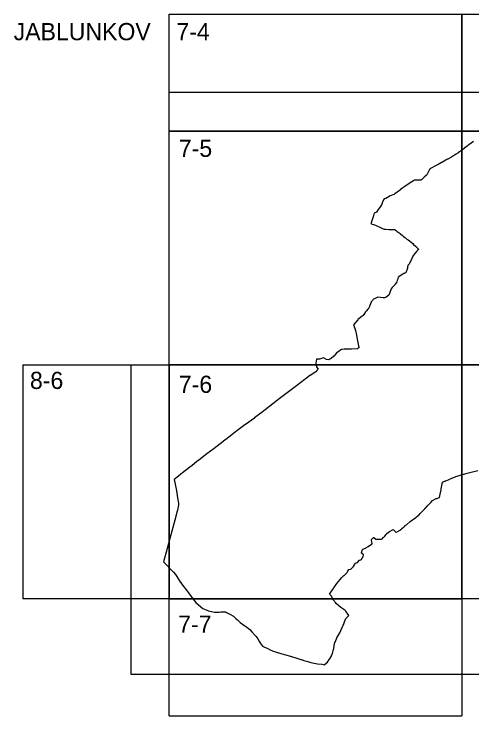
# Model space of a CAD drawing. Extents: x -449577 to -436680, y -1132317 to -1125726.
# Drawn here: x -444031.6 to -443787.2, y -1131943.6 to -1131568.6 of the extents above; entities that cross this region are included whole.
import ezdxf

# ---------------------------------------------------------------- set-up
doc = ezdxf.new("R2010")
doc.units = 0
for name, color, linetype in [('Vrstva 1', 7, 'Continuous'), ('Vrstva 10', 7, 'Continuous'), ('Vrstva 4', 7, 'Continuous')]:
    doc.layers.add(name, color=color, linetype=linetype)

msp = doc.modelspace()

# ---------------------------------------------------------------- linework, layer by layer
at = {"layer": 'Vrstva 1'}
for points in [[(-443786.38, -1131636.64), (-443787.59, -1131637.6), (-443787.59, -1131637.6), (-443788.74, -1131638.47), (-443789.31, -1131638.9), (-443789.89, -1131639.34), (-443790.05, -1131639.46), (-443792.18, -1131641.1), (-443793.25, -1131641.92), (-443793.72, -1131642.26), (-443794.48, -1131642.77), (-443794.73, -1131642.93), (-443795.32, -1131643.32), (-443795.36, -1131643.35), (-443795.57, -1131643.49), (-443796.48, -1131644.09), (-443796.49, -1131644.09), (-443796.96, -1131644.35), (-443797.11, -1131644.43), (-443797.29, -1131644.53), (-443797.75, -1131644.78), (-443797.93, -1131644.89), (-443798.09, -1131644.98), (-443798.19, -1131645.04), (-443798.43, -1131645.18), (-443800.09, -1131646.12), (-443800.26, -1131646.21), (-443800.49, -1131646.34), (-443802.96, -1131647.74), (-443803.08, -1131647.81), (-443805.19, -1131648.94), (-443806.21, -1131649.49), (-443809.55, -1131651.3), (-443809.72, -1131651.6), (-443809.78, -1131651.71), (-443810.56, -1131653.17), (-443811.24, -1131654.49), (-443811.38, -1131654.62), (-443811.47, -1131654.7), (-443812.61, -1131655.74), (-443814.12, -1131657.12), (-443814.29, -1131657.27), (-443814.29, -1131657.28), (-443814.76, -1131657.29), (-443817.95, -1131657.38), (-443817.96, -1131657.38), (-443818.39, -1131657.67), (-443819.22, -1131658.24), (-443821.69, -1131659.9), (-443821.73, -1131659.92), (-443821.97, -1131660.1), (-443822.24, -1131660.3), (-443825.22, -1131662.43), (-443825.29, -1131662.48), (-443828.29, -1131664.66), (-443828.76, -1131665), (-443828.92, -1131665.06), (-443830.86, -1131665.78), (-443830.87, -1131665.78), (-443831.26, -1131666.02), (-443833.14, -1131667.18), (-443834.06, -1131667.39), (-443834.31, -1131667.9), (-443835.07, -1131669.41), (-443835.08, -1131669.42), (-443835.15, -1131669.68), (-443835.35, -1131670.52), (-443836.18, -1131671.63), (-443837.55, -1131673.58), (-443838.11, -1131674.39), (-443838.14, -1131674.41), (-443839.3, -1131675.05), (-443839.4, -1131675.11), (-443839.47, -1131675.5), (-443839.62, -1131676.31), (-443839.67, -1131676.5), (-443840.96, -1131680.08), (-443841.13, -1131680.56), (-443841.1, -1131680.55), (-443841.08, -1131680.54), (-443840.4, -1131680.8), (-443838.59, -1131681.46), (-443837.97, -1131681.75), (-443835.68, -1131682.83), (-443835.66, -1131682.83), (-443834.5, -1131683.3), (-443834.03, -1131683.48), (-443834, -1131683.49), (-443833.57, -1131683.52), (-443833.43, -1131683.53), (-443833.21, -1131683.55), (-443831.61, -1131683.65), (-443830.57, -1131683.72), (-443829.52, -1131683.69), (-443828.68, -1131683.66), (-443828.67, -1131683.66), (-443828.39, -1131683.81), (-443828.02, -1131684.07), (-443827.47, -1131684.45), (-443827.08, -1131684.73), (-443825.52, -1131685.87), (-443825.35, -1131685.99), (-443824.24, -1131686.91), (-443823.85, -1131687.23), (-443823.67, -1131687.38), (-443822.92, -1131687.99), (-443822.65, -1131688.22), (-443822.05, -1131688.71), (-443821.83, -1131688.89), (-443821.19, -1131689.31), (-443820.44, -1131689.81), (-443820.41, -1131689.83), (-443819.65, -1131690.51), (-443818.77, -1131691.29), (-443818.33, -1131691.67), (-443817.32, -1131692.56), (-443817.06, -1131692.79), (-443817.01, -1131692.84), (-443816.91, -1131692.94), (-443816.9, -1131692.95), (-443816.81, -1131693.05), (-443816.78, -1131693.08), (-443815.73, -1131694.31), (-443815.74, -1131694.32), (-443816.18, -1131694.81), (-443816.24, -1131694.88), (-443816.81, -1131695.51), (-443817.63, -1131696.57), (-443817.8, -1131696.78), (-443818.36, -1131697.5), (-443818.66, -1131698.03), (-443818.68, -1131698.07), (-443818.69, -1131698.09), (-443818.82, -1131698.37), (-443819.62, -1131700.04), (-443819.93, -1131700.68), (-443820.55, -1131701.97), (-443820.66, -1131702.21), (-443820.67, -1131702.21), (-443820.71, -1131702.24), (-443821, -1131702.44), (-443821.08, -1131702.48), (-443821.13, -1131702.58), (-443821.22, -1131702.78), (-443821.31, -1131703.06), (-443821.48, -1131703.62), (-443821.49, -1131703.64), (-443821.61, -1131704.14), (-443821.63, -1131704.21), (-443821.62, -1131704.27), (-443821.61, -1131704.35), (-443821.61, -1131704.42), (-443821.62, -1131704.47), (-443822.5, -1131706.8), (-443822.52, -1131706.85), (-443822.54, -1131706.89), (-443822.55, -1131706.9), (-443823.25, -1131707.2), (-443823.5, -1131707.31), (-443823.97, -1131707.55), (-443826.58, -1131709.24), (-443826.58, -1131709.24), (-443826.95, -1131710.55), (-443827.03, -1131710.81), (-443827.14, -1131711.23), (-443827.2, -1131711.44), (-443827.2, -1131711.45), (-443827.19, -1131711.45), (-443827.02, -1131711.61), (-443827.03, -1131711.62), (-443827.39, -1131712.01), (-443828.19, -1131713.01), (-443828.2, -1131713.02), (-443828.41, -1131713.27), (-443828.41, -1131713.28), (-443828.53, -1131713.43), (-443829.69, -1131714.78), (-443830.23, -1131715.41), (-443830.99, -1131717.36), (-443831.37, -1131718.38), (-443831.5, -1131718.73), (-443833.03, -1131719.83), (-443833.65, -1131720.27), (-443833.83, -1131720.31), (-443833.85, -1131720.31), (-443834.48, -1131720.22), (-443837.32, -1131719.8), (-443837.81, -1131720.04), (-443839.14, -1131720.68), (-443839.68, -1131720.94), (-443839.71, -1131720.97), (-443840.14, -1131721.38), (-443840.31, -1131721.6), (-443840.97, -1131722.45), (-443840.97, -1131722.46), (-443841.64, -1131724.26), (-443842.21, -1131725.76), (-443842.21, -1131725.76), (-443842.35, -1131725.98), (-443842.68, -1131726.35), (-443843.4, -1131727.15), (-443844.1, -1131727.92), (-443844.11, -1131727.94), (-443844.24, -1131728.13), (-443845.31, -1131729.7), (-443845.78, -1131730.08), (-443847.35, -1131731.34), (-443848.02, -1131731.88), (-443848.12, -1131731.96), (-443848.15, -1131732), (-443849.27, -1131733.43), (-443850.41, -1131734.74), (-443850.26, -1131734.91), (-443850.25, -1131734.94), (-443850.25, -1131734.95), (-443849.24, -1131737.71), (-443848.96, -1131739.37), (-443848.64, -1131741.32), (-443848.23, -1131743.28), (-443847.5, -1131746.78), (-443847.46, -1131746.98), (-443848.11, -1131747.32), (-443848.23, -1131747.39), (-443851.4, -1131747.65), (-443851.56, -1131747.65), (-443853.05, -1131747.62), (-443855.44, -1131747.6), (-443856.72, -1131747.87), (-443857.32, -1131748.14), (-443858.3, -1131748.94), (-443859.6, -1131749.81), (-443859.69, -1131749.92), (-443860.85, -1131751.34), (-443862.3, -1131752.68), (-443862.99, -1131753), (-443863.59, -1131753.28), (-443864.76, -1131753.21), (-443866.37, -1131752.36), (-443868.61, -1131753.03), (-443870.09, -1131753), (-443870.47, -1131755.11), (-443870.48, -1131755.13), (-443870.49, -1131755.22), (-443870.2, -1131757.03), (-443869.23, -1131758.35), (-443869.22, -1131758.37), (-443869.96, -1131759.12), (-443870.57, -1131759.68), (-443870.82, -1131759.91), (-443871.62, -1131760.54), (-443873.55, -1131761.77), (-443873.61, -1131761.81), (-443875.58, -1131763.34), (-443875.64, -1131763.38), (-443876.13, -1131763.76), (-443880.79, -1131767.22), (-443880.82, -1131767.25), (-443885.77, -1131771.01), (-443890.03, -1131774.26), (-443890.91, -1131774.92), (-443893.48, -1131776.86), (-443897.48, -1131779.99), (-443899.92, -1131781.86), (-443903.23, -1131784.39), (-443903.28, -1131784.43), (-443908.07, -1131787.94), (-443908.3, -1131788.12), (-443911.91, -1131790.8), (-443914.3, -1131792.62), (-443916.27, -1131794.1), (-443918.59, -1131795.85), (-443918.82, -1131796.02), (-443919.95, -1131796.91), (-443924.77, -1131800.71), (-443928.66, -1131803.66), (-443932.88, -1131806.91), (-443934.17, -1131807.91), (-443936.56, -1131809.79), (-443937.74, -1131810.71), (-443941.68, -1131813.76), (-443942.61, -1131814.47), (-443943.85, -1131815.43), (-443946.17, -1131817.23), (-443946.17, -1131817.23), (-443946.13, -1131817.41), (-443945.84, -1131818.79), (-443945.81, -1131818.95), (-443945.28, -1131821.49), (-443945.12, -1131822.22), (-443945.12, -1131822.26), (-443944.19, -1131828.14), (-443944.18, -1131828.17), (-443943.88, -1131829.9), (-443943.88, -1131829.92), (-443943.82, -1131830.29), (-443943.76, -1131830.71), (-443943.79, -1131831.08), (-443943.94, -1131831.81), (-443944.32, -1131833.6), (-443944.61, -1131834.78), (-443944.63, -1131834.83), (-443945.74, -1131839), (-443947.84, -1131846.88), (-443949.83, -1131854.1), (-443951.76, -1131861.2), (-443951.77, -1131861.24), (-443946.49, -1131866.84), (-443945.44, -1131867.97), (-443944.68, -1131869.19), (-443942.66, -1131872.25), (-443942.61, -1131872.32), (-443941.6, -1131873.73), (-443941.44, -1131873.94), (-443939.56, -1131876.42), (-443938.99, -1131877.16), (-443938.96, -1131877.2), (-443938.44, -1131877.92), (-443937.06, -1131879.82), (-443936.73, -1131880.27), (-443934.58, -1131882.99), (-443933.18, -1131884.21), (-443930.78, -1131886.19), (-443929.04, -1131886.94), (-443927.85, -1131887.46), (-443927.72, -1131887.51), (-443926.39, -1131887.79), (-443926.25, -1131887.82), (-443924.63, -1131888.15), (-443924.6, -1131888.15), (-443923.64, -1131888.13), (-443923.26, -1131888.13), (-443922.74, -1131888.12), (-443922.06, -1131888.11), (-443921.15, -1131888.07), (-443919.2, -1131887.91), (-443918.75, -1131887.98), (-443918.09, -1131888.33), (-443916.37, -1131889.28), (-443914.41, -1131890.38), (-443913.89, -1131890.86), (-443913.17, -1131891.54), (-443912.37, -1131892.29), (-443911.05, -1131893.59), (-443910.91, -1131893.69), (-443909.72, -1131894.54), (-443907.31, -1131896.25), (-443905.67, -1131897.43), (-443904.62, -1131898.61), (-443902.98, -1131900.43), (-443902.34, -1131901.14), (-443901.98, -1131901.73), (-443901.52, -1131902.47), (-443900.58, -1131903.94), (-443899.95, -1131904.86), (-443898.91, -1131906.3), (-443897.84, -1131906.81), (-443896.46, -1131907.46), (-443895.15, -1131908.07), (-443893.18, -1131908.96), (-443892.05, -1131909.31), (-443890.33, -1131909.88), (-443890.18, -1131909.93), (-443889.09, -1131910.25), (-443887.67, -1131910.67), (-443887.66, -1131910.67), (-443887.45, -1131910.73), (-443887.39, -1131910.75), (-443886.53, -1131911.01), (-443884.14, -1131911.7), (-443884.02, -1131911.74), (-443883.54, -1131911.88), (-443880.61, -1131912.75), (-443877.92, -1131913.58), (-443877.58, -1131913.68), (-443876.82, -1131913.91), (-443874.81, -1131914.53), (-443873.08, -1131915.08), (-443869.62, -1131915.82)], [(-443869.62, -1131915.82), (-443867.23, -1131916.01), (-443866.03, -1131916.24), (-443865.92, -1131916.15), (-443864.34, -1131914.88), (-443863.31, -1131913.4), (-443863.2, -1131913.25), (-443862.68, -1131912.49), (-443862.57, -1131912.32), (-443862.43, -1131912.09), (-443862.05, -1131911.46), (-443861.78, -1131910.63), (-443861.76, -1131910.56), (-443861.74, -1131910.51), (-443861.71, -1131910.4), (-443861.68, -1131910.31), (-443861.68, -1131910.3), (-443861.05, -1131908.1), (-443860.91, -1131907.58), (-443860.46, -1131904.83), (-443860.46, -1131904.83), (-443860.27, -1131904.39), (-443860.01, -1131903.77), (-443859.22, -1131901.94), (-443857.65, -1131899.29), (-443855.9, -1131895.16), (-443855.58, -1131894.52), (-443855.54, -1131894.39), (-443855.15, -1131893.29), (-443854.56, -1131891.62), (-443852.88, -1131889.91), (-443853.81, -1131888.67), (-443853.87, -1131888.58), (-443853.92, -1131888.52), (-443853.95, -1131888.48), (-443854.02, -1131888.38), (-443854.07, -1131888.3), (-443854.15, -1131888.18), (-443854.51, -1131887.66), (-443854.88, -1131887.2), (-443855.45, -1131886.83), (-443855.55, -1131886.77), (-443857.2, -1131885.7), (-443859.39, -1131883.76), (-443859.52, -1131883.59), (-443859.55, -1131883.55), (-443859.63, -1131883.45), (-443859.97, -1131883.03), (-443860.3, -1131882.62), (-443860.56, -1131882.3), (-443861.04, -1131881.71), (-443861.12, -1131881.61), (-443861.62, -1131880.65), (-443861.91, -1131880.09), (-443862.14, -1131879.66), (-443862.19, -1131879.57), (-443862.23, -1131879.52), (-443862.49, -1131879.23), (-443862.69, -1131879), (-443862.95, -1131878.71), (-443863.17, -1131878.46), (-443861.31, -1131875.72), (-443861.22, -1131875.6), (-443860.9, -1131875.15), (-443860.58, -1131874.71), (-443859.25, -1131872.88), (-443856.57, -1131869.62), (-443856.22, -1131869.3), (-443855.51, -1131868.6), (-443855.4, -1131868.51), (-443855.21, -1131868.37), (-443854.61, -1131867.89), (-443853.75, -1131867.05), (-443853.34, -1131866.29), (-443852.87, -1131865.42), (-443851.82, -1131865.18), (-443850.42, -1131863.75), (-443849.88, -1131862.9), (-443849.87, -1131862.89), (-443849.87, -1131862.87), (-443849.66, -1131862.54), (-443849.61, -1131862.46), (-443849.37, -1131862.07), (-443848.21, -1131861.63), (-443847.19, -1131860.45), (-443846.66, -1131860.25), (-443846.54, -1131860.2), (-443846.12, -1131860.04), (-443845.9, -1131859.65), (-443845.85, -1131859.56), (-443845.68, -1131859.26), (-443845.27, -1131858.52), (-443845.07, -1131857.61), (-443845.07, -1131857.59), (-443845.06, -1131857.58), (-443846.11, -1131856.59), (-443846.13, -1131856.58), (-443846.14, -1131856.56), (-443846.19, -1131856.52), (-443845.54, -1131854.72), (-443845.47, -1131854.52), (-443845.31, -1131854.46), (-443844.58, -1131854.17), (-443843.89, -1131853.9), (-443843.77, -1131853.85), (-443842.56, -1131853.14), (-443842.44, -1131853.06), (-443842.44, -1131853.06), (-443842.43, -1131853.05), (-443842.31, -1131852.98), (-443840.45, -1131851.58), (-443840.45, -1131851.54), (-443840.48, -1131851.38), (-443840.55, -1131850.9), (-443840.61, -1131850.55), (-443840.71, -1131849.93), (-443840.73, -1131849.82), (-443840.75, -1131849.69), (-443840.77, -1131849.52), (-443840.8, -1131849.38), (-443840.26, -1131848.82), (-443839.7, -1131848.25), (-443839.66, -1131848.2), (-443839.52, -1131848.3), (-443838.52, -1131849.09), (-443837.84, -1131849.1), (-443837.78, -1131849.1), (-443837.53, -1131849.11), (-443837.37, -1131849.11), (-443836.06, -1131849.13), (-443835.43, -1131849.15), (-443835.16, -1131848.99), (-443835.13, -1131848.97), (-443835.01, -1131848.9), (-443834.87, -1131848.81), (-443834.83, -1131848.78), (-443834.29, -1131848.18), (-443834.18, -1131848.06), (-443834.09, -1131847.96), (-443833.92, -1131847.78), (-443833.84, -1131847.69), (-443833.73, -1131847.57), (-443833.7, -1131847.53), (-443833.67, -1131847.5), (-443833.62, -1131847.44), (-443833.53, -1131847.33), (-443833.13, -1131846.83), (-443832.92, -1131846.57), (-443832.67, -1131846.25), (-443832.56, -1131846.17), (-443831.1, -1131845.1), (-443830.89, -1131844.97), (-443829.53, -1131844.2), (-443829.13, -1131843.97), (-443829.13, -1131843.97), (-443828.99, -1131844.12), (-443828.28, -1131844.83), (-443827.91, -1131845.21), (-443827.73, -1131845.38), (-443827.58, -1131845.53), (-443827.49, -1131845.49), (-443826.21, -1131844.72), (-443826.12, -1131844.67), (-443825.19, -1131844.11), (-443825.15, -1131844.08), (-443824.82, -1131843.79), (-443824.77, -1131843.75), (-443824.6, -1131843.6), (-443824.59, -1131843.59), (-443824.59, -1131843.59), (-443824.55, -1131843.55), (-443824.51, -1131843.51), (-443823.62, -1131842.7), (-443823.6, -1131842.69), (-443823.01, -1131842.15), (-443822.9, -1131842.06), (-443822.79, -1131841.96), (-443822.79, -1131841.96), (-443822.78, -1131841.96), (-443822.78, -1131841.96), (-443822.78, -1131841.95), (-443822.77, -1131841.95), (-443822.76, -1131841.94), (-443822.76, -1131841.94), (-443822.75, -1131841.93), (-443822.75, -1131841.93), (-443822.74, -1131841.93), (-443822.74, -1131841.93), (-443822.16, -1131841.44), (-443820.17, -1131839.76), (-443818.97, -1131838.91), (-443818.85, -1131838.83), (-443818.8, -1131838.79), (-443818.78, -1131838.78), (-443818.73, -1131838.75), (-443818.37, -1131838.48), (-443817.13, -1131837.54), (-443816.95, -1131837.4), (-443816.74, -1131837.24), (-443816.72, -1131837.22), (-443815.84, -1131836.55), (-443815.49, -1131836.28), (-443815.44, -1131836.22), (-443815.35, -1131836.12), (-443814.71, -1131835.44), (-443813.81, -1131834.46), (-443812.45, -1131833.05), (-443812.23, -1131832.82), (-443811.98, -1131832.54), (-443811.14, -1131831.59), (-443810.85, -1131831.27), (-443810.65, -1131831.06), (-443810.36, -1131830.74), (-443809.18, -1131829.55), (-443808.25, -1131828.53), (-443806.19, -1131827.52), (-443806.03, -1131827.47), (-443805.83, -1131827.39), (-443804.39, -1131826.9), (-443804.24, -1131826.03), (-443804.08, -1131825.16), (-443803.66, -1131822.79), (-443803.58, -1131822.32), (-443803.25, -1131820.44), (-443803.05, -1131819.56), (-443803.02, -1131819.44), (-443802.97, -1131819.25), (-443802.96, -1131819.21), (-443802.94, -1131819.14), (-443802.93, -1131819.1), (-443802.92, -1131819.05), (-443802.91, -1131819.01), (-443802.9, -1131818.99), (-443802.84, -1131818.78), (-443801.76, -1131818.24), (-443801.47, -1131818.1), (-443801.45, -1131818.09), (-443801.2, -1131817.96), (-443801.15, -1131817.94), (-443799.38, -1131817.22), (-443799.35, -1131817.21), (-443799.32, -1131817.19), (-443798.52, -1131816.88), (-443797.56, -1131816.48), (-443796.75, -1131816.14), (-443795.81, -1131815.75), (-443795.73, -1131815.72), (-443795.12, -1131815.48), (-443795.27, -1131815.64), (-443795.03, -1131815.55), (-443794.54, -1131815.35), (-443794.01, -1131815.19), (-443792.31, -1131814.67), (-443791.72, -1131814.5), (-443791.27, -1131814.38), (-443790.38, -1131814.13), (-443789.07, -1131813.75), (-443787.53, -1131813.29), (-443783.99, -1131812.42)]]:
    msp.add_lwpolyline(points, dxfattribs=at)
at = {"layer": 'Vrstva 10'}
msp.add_lwpolyline([(-443636.23, -1131610.43), (-443636.23, -1131921.41), (-443969.1, -1131921.41), (-443969.1, -1131756.11), (-443948.73, -1131756.11), (-443948.73, -1131631.11), (-443948.73, -1131610.43), (-443636.23, -1131610.43)], dxfattribs=at)
at = {"layer": 'Vrstva 4'}
for p, q in [((-443948.73, -1131568.61), (-443636.23, -1131568.61)), ((-444026.86, -1131756.11), (-444026.86, -1131881.11)), ((-443948.73, -1131943.61), (-443792.48, -1131943.61))]:
    msp.add_line(p, q, dxfattribs=at)
for points in [[(-443792.48, -1131568.61), (-443792.48, -1131631.11), (-443948.73, -1131631.11), (-443948.73, -1131568.61)], [(-443636.23, -1131568.61), (-443636.23, -1131631.11), (-443792.48, -1131631.11), (-443792.48, -1131568.61)], [(-444026.86, -1131756.11), (-443948.73, -1131756.11), (-443948.73, -1131881.11), (-444026.86, -1131881.11)], [(-443948.73, -1131943.61), (-443948.73, -1131881.11), (-443792.48, -1131881.11), (-443792.48, -1131943.61)]]:
    msp.add_lwpolyline(points, dxfattribs=at)
for points in [[(-443792.48, -1131631.11), (-443792.48, -1131756.11), (-443948.73, -1131756.11), (-443948.73, -1131631.11)], [(-443636.23, -1131631.11), (-443636.23, -1131756.11), (-443792.48, -1131756.11), (-443792.48, -1131631.11)], [(-443792.48, -1131756.11), (-443792.48, -1131881.11), (-443948.73, -1131881.11), (-443948.73, -1131756.11)], [(-443636.23, -1131756.11), (-443636.23, -1131881.11), (-443792.48, -1131881.11), (-443792.48, -1131756.11)]]:
    msp.add_lwpolyline(points, close=True, dxfattribs=at)

# ---------------------------------------------------------------- texts
at = {"layer": 'Vrstva 1'}
for s, p in [('JABLUNKOV', (-444031.77, -1131582.61)), ('7-4', (-443944.92, -1131582.61)), ('7-5', (-443943.61, -1131644.95)), ('8-6', (-444023.08, -1131768.92)), ('7-6', (-443943.61, -1131771.02)), ('7-7', (-443943.97, -1131899.19))]:
    msp.add_text(s, height=9.2, dxfattribs=at).set_placement(p)

doc.saveas('drawing.dxf')
